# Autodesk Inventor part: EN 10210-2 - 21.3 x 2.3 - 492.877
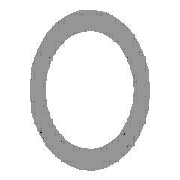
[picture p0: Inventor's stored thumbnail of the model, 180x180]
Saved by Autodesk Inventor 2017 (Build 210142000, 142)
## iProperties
Created: 2017-11
Part Number: EN 10210-2 - 21.3 x 2.3 - 492.877
Material: Steel, Mild
Description: Pipe
Document SubType Name: Modeling
Standard: DIN
Designer: iusti
Standard Revision: 2006-07
Standards Organization: DIN
Language: en-US
Size Designation: 21.3 x 2.3
Categories: <MemberInstance><Categories><Category DisplayName="Structural Shapes" InternalName="089c4875-fa83-4c05-b084-43b9cc11f5ed" Mnemonic="GRDR"><CategoryParameter Dis
Stock Number: 21.3 x 2.3
Density: 7.85 g/cm^3
Appearance: Semi-Polished
_CCFamilyMember: 1
_CCFamilyDisplayName: DIN EN 10210-2 - Pipe
_FrameMemberDoc: Frame Member File
_Version: 15.0.0
_GetPNFromCC: 1
IsCustomPart: 1
Author: iusti
G_L: 492.877 mm
G_W: 21.300 mm
G_H: 21.300 mm
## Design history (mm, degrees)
node "Start plane"
node "End plane"
sketch "Sketch"
  geometry: C1 r 8.35 at (0, 0); C2 r 10.65 at (0, 0); 2 further points
  constraints: 3 coincident, 2 centre point
  dimensions: "d0" = 21.3 diameter of C2 (= G_H); "d1" = 2.3 radial gap between concentric circles of C2 C1 (= G_T)
extrude "Body" new body sketch "Sketch" stored distance "d2" = 492.87692 (= G_L); taper "d3" = 0 deg
node "Driven Length"
  sketch "Sketch3"
    geometry: L1 (0, 0)-(10, 0) reference
    constraints: 2 end point, 1 horizontal
  workplane "Work Plane3"
  sketch "Sketch4"
    geometry: L1 (-2, 0)-(12, 0) reference; L2 (-2, 492.877)-(12, 492.877) reference
    dimensions: "d7" = 492.87692 distance between parallel lines of L1 L2 (derived)
body "Solid1"
other parameters: "G_H" = 21.3 [user parameter; used in 1 equation term], "G_T" = 2.3 [user parameter; used in 1 equation term], "G_L" = 492.87692 (= d7) [user parameter; used in 1 equation term], "G_OFFSET_START" = 0 [user parameter; used in 1 equation term], "G_OFFSET_END" = 0 [user parameter; used in 1 equation term], "d4" = 0 (computed from G_OFFSET_START), "d5" = 492.87692 (= G_OFFSET_END + B_L), "B_L" = 492.87692 [user parameter; used in 1 equation term], "d6" = 90 deg
